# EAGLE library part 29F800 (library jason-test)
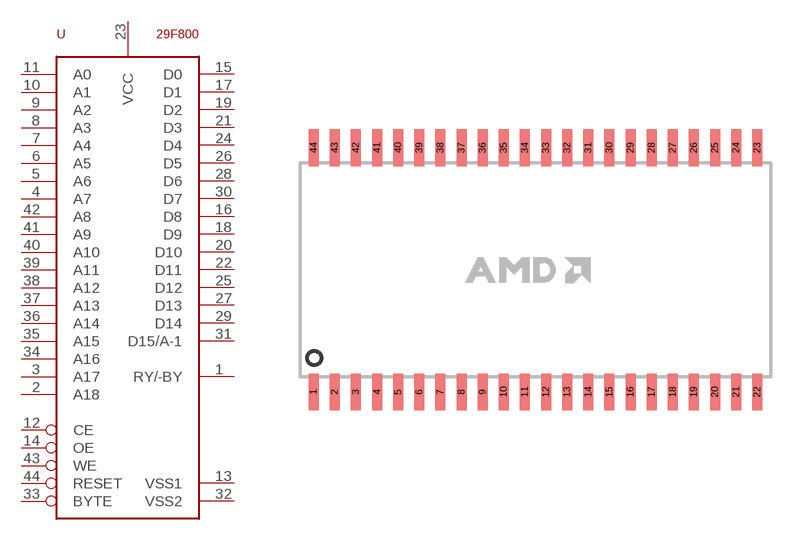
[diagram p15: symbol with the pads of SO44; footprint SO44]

Designator prefix -

## 29F800  [SO44]
1  RY/-BY  out
2  A18  in
3  A17  in
4  A7  in
5  A6  in
6  A5  in
7  A4  in
8  A3  in
9  A2  in
10  A1  in
11  A0  in
12  CE  in
13  VSS1  pwr
14  OE  in
15  D0  hiz
16  D8  hiz
17  D1  hiz
18  D9  hiz
19  D2  hiz
20  D10  hiz
21  D3  hiz
22  D11  hiz
23  VCC  pwr
24  D4  hiz
25  D12  hiz
26  D5  hiz
27  D13  hiz
28  D6  hiz
29  D14  hiz
30  D7  hiz
31  D15/A-1  hiz
32  VSS2  pwr
33  BYTE  in
34  A16  in
35  A15  in
36  A14  in
37  A13  in
38  A12  in
39  A11  in
40  A10  in
41  A9  in
42  A8  in
43  WE  in
44  RESET  in

## Footprint SO44 (pad centres in mm)
Small Outline Package
smd 0.6 x 2.2: 1 -13.335,-7.34; 2 -12.065,-7.34; 3 -10.795,-7.34; 4 -9.525,-7.34; 5 -8.255,-7.34; 6 -6.985,-7.34; 7 -5.715,-7.34; 8 -4.445,-7.34; 9 -3.175,-7.34; 10 -1.905,-7.34; 11 -0.635,-7.34; 12 0.635,-7.34; 13 1.905,-7.34; 14 3.175,-7.34; 15 4.445,-7.34; 16 5.715,-7.34; 17 6.985,-7.34; 18 8.255,-7.34; 19 9.525,-7.34; 20 10.795,-7.34; 21 12.065,-7.34; 22 13.335,-7.34; 23 13.335,7.34; 24 12.065,7.34; 25 10.795,7.34; 26 9.525,7.34; 27 8.255,7.34; 28 6.985,7.34; 29 5.715,7.34; 30 4.445,7.34; 31 3.175,7.34; 32 1.905,7.34; 33 0.635,7.34; 34 -0.635,7.34; 35 -1.905,7.34; 36 -3.175,7.34; 37 -4.445,7.34; 38 -5.715,7.34; 39 -6.985,7.34; 40 -8.255,7.34; 41 -9.525,7.34; 42 -10.795,7.34; 43 -12.065,7.34; 44 -13.335,7.34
